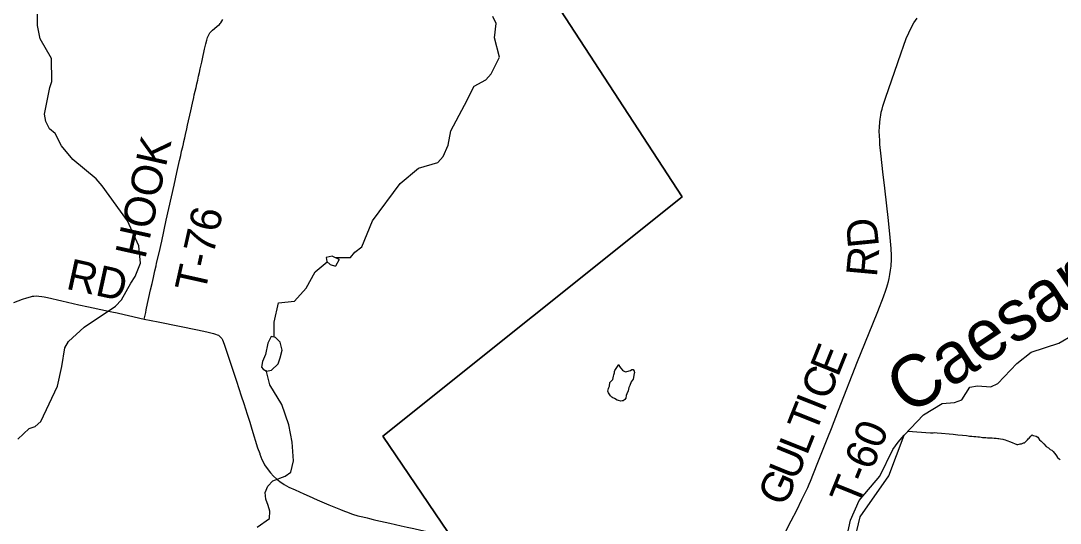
# Model space of a CAD drawing. Extents: x 1410790 to 1770854, y 448063 to 770588.
# Drawn here: x 1576526 to 1586619, y 599085 to 603957 of the extents above; entities that cross this region are included whole.
import ezdxf

# ---------------------------------------------------------------- set-up
doc = ezdxf.new("R2010")
doc.units = 0
for name, color, linetype in [('GM_X_Major_River', 7, 'Continuous'), ('GM_X_Major_River_Text', 7, 'Continuous'), ('GM_X_Minor_Lake', 7, 'Continuous'), ('GM_X_Minor_River', 7, 'Continuous'), ('GM_X_Township', 7, 'Continuous'), ('GM_X_Township_Road', 7, 'Continuous'), ('GM_X_Township_Road_Text', 7, 'Continuous')]:
    doc.layers.add(name, color=color, linetype=linetype)

msp = doc.modelspace()

# ---------------------------------------------------------------- linework, layer by layer
at = {"layer": 'GM_X_Major_River'}
for points in [[(1585103, 599938), (1585291, 600136), (1585474, 600246), (1585594, 600256), (1585665, 600280), (1585742, 600403), (1585816, 600417), (1585944, 600408), (1586013, 600441), (1586199, 600635), (1586338, 600744), (1586606, 600832), (1586872, 600985)], [(1584549, 598964), (1584584, 599114), (1584666, 599304), (1584868, 599542), (1584994, 599800), (1585047, 599871), (1585103, 599938)], [(1584615, 598887), (1584675, 599146), (1584954, 599544), (1585103, 599938)]]:
    msp.add_lwpolyline(points, dxfattribs=at)
at = {"layer": 'GM_X_Minor_Lake'}
for points in [[(1579618, 601642), (1579550, 601675), (1579492, 601660), (1579497, 601622), (1579530, 601594), (1579582, 601577)], [(1579618, 601642), (1579582, 601577)], [(1578962, 600569), (1579025, 600630), (1579046, 600690), (1579063, 600763), (1579046, 600840), (1578999, 600887), (1578957, 600896), (1578926, 600830), (1578902, 600720), (1578873, 600654)], [(1578873, 600654), (1578864, 600597), (1578878, 600578), (1578912, 600560), (1578962, 600569)], [(1582333, 600625), (1582341, 600603), (1582353, 600589), (1582369, 600569), (1582379, 600563), (1582391, 600556), (1582401, 600552), (1582411, 600556), (1582423, 600560), (1582435, 600562), (1582445, 600566), (1582459, 600574), (1582471, 600576), (1582483, 600558), (1582485, 600545), (1582483, 600535), (1582472, 600483), (1582454, 600456), (1582441, 600420), (1582431, 600400), (1582425, 600368), (1582412, 600338), (1582404, 600324), (1582400, 600296), (1582392, 600284), (1582374, 600270), (1582364, 600270), (1582354, 600268), (1582330, 600276), (1582316, 600278), (1582292, 600295), (1582276, 600301), (1582266, 600307), (1582252, 600321), (1582246, 600331), (1582234, 600350), (1582226, 600364), (1582228, 600378), (1582233, 600390), (1582235, 600400), (1582241, 600414), (1582247, 600448), (1582263, 600466), (1582274, 600477), (1582280, 600511), (1582286, 600525), (1582290, 600543), (1582292, 600555), (1582295, 600567), (1582333, 600625)]]:
    msp.add_lwpolyline(points, dxfattribs=at)
at = {"layer": 'GM_X_Minor_River'}
for points in [[(1576498, 599899), (1576606, 600002), (1576667, 600021), (1576722, 600072), (1576884, 600412), (1576923, 600604), (1576955, 600784), (1576990, 600847), (1577142, 600987), (1577445, 601190), (1577504, 601251), (1577595, 601412), (1577636, 601478), (1577690, 601607), (1577671, 601776), (1577561, 602016), (1577316, 602357), (1577259, 602426), (1577030, 602613), (1576922, 602745), (1576860, 602864), (1576804, 602909), (1576768, 602980), (1576755, 603053), (1576807, 603310), (1576826, 603370), (1576824, 603593), (1576713, 603783), (1576689, 603912), (1576689, 604022)], [(1579580, 601660), (1579728, 601660), (1579769, 601714), (1579838, 601765), (1579941, 602018), (1580211, 602378), (1580388, 602529), (1580574, 602582), (1580629, 602641), (1580677, 602751), (1580703, 602891), (1580834, 603139), (1580927, 603324), (1581041, 603386), (1581092, 603442), (1581173, 603605), (1581126, 603792), (1581142, 603930), (1581109, 603999)], [(1578985, 600890), (1578986, 601033), (1579027, 601223), (1579184, 601237), (1579296, 601363), (1579385, 601524), (1579500, 601619)], [(1578821, 599045), (1578941, 599131), (1578944, 599202), (1578927, 599256), (1578904, 599317), (1578899, 599381), (1578926, 599443), (1578973, 599494), (1579092, 599540), (1579149, 599579), (1579173, 599689), (1579160, 599872), (1579129, 600037), (1579060, 600236), (1578943, 600425), (1578910, 600570)], [(1585139, 599976), (1585360, 599960), (1585386, 599962), (1585402, 599964), (1585424, 599962), (1585466, 599957), (1585540, 599950), (1585580, 599948), (1585624, 599943), (1585670, 599939), (1585710, 599935), (1585726, 599932), (1585738, 599930), (1585748, 599930), (1585760, 599928), (1585780, 599926), (1585800, 599924), (1585820, 599921), (1585836, 599921), (1585852, 599919), (1585864, 599917), (1585879, 599917), (1585897, 599915), (1585913, 599914), (1585935, 599912), (1585957, 599912), (1585977, 599910), (1585997, 599908), (1586013, 599907), (1586023, 599907), (1586039, 599903), (1586061, 599899), (1586071, 599895), (1586083, 599893), (1586101, 599886), (1586111, 599884), (1586127, 599878), (1586137, 599874), (1586198, 599849), (1586208, 599847), (1586220, 599851), (1586231, 599853), (1586243, 599855), (1586263, 599863), (1586273, 599865), (1586285, 599878), (1586301, 599892), (1586309, 599902), (1586319, 599908), (1586334, 599930), (1586346, 599940), (1586356, 599934), (1586386, 599928), (1586402, 599919), (1586419, 599893), (1586435, 599879), (1586449, 599865), (1586461, 599855), (1586483, 599830), (1586505, 599814), (1586522, 599800), (1586536, 599792), (1586550, 599779), (1586564, 599763), (1586578, 599749), (1586582, 599739), (1586594, 599723), (1586608, 599709), (1586620, 599701)]]:
    msp.add_lwpolyline(points, dxfattribs=at)
at = {"layer": 'GM_X_Township'}
for points in [[(1587401, 595462), (1585823, 594285), (1584421, 596026), (1582893, 594860), (1582879, 594881), (1581973, 596138), (1581379, 596962), (1581560, 597014), (1581832, 596995), (1581884, 597016), (1581927, 597072), (1581946, 597129), (1580737, 598905), (1580040, 599928), (1582947, 602250), (1581717, 604136)], [(1581717, 604136), (1582947, 602250), (1580040, 599928), (1580737, 598905)]]:
    msp.add_lwpolyline(points, dxfattribs=at)
at = {"layer": 'GM_X_Township_Road'}
for points in [[(1577725, 601064), (1577739, 601129), (1577745, 601155), (1577758, 601216), (1577770, 601273), (1577787, 601347), (1577801, 601408), (1577814, 601468), (1577828, 601533), (1577839, 601581), (1577845, 601606), (1577869, 601708), (1577894, 601820), (1577939, 602025), (1577965, 602137), (1578016, 602364), (1578042, 602486), (1578068, 602601), (1578079, 602652), (1578088, 602694), (1578098, 602735), (1578105, 602764), (1578110, 602787), (1578118, 602822), (1578125, 602854), (1578139, 602911), (1578146, 602946), (1578176, 603084), (1578193, 603158), (1578206, 603215), (1578211, 603238), (1578220, 603276), (1578228, 603311), (1578237, 603346), (1578244, 603381), (1578253, 603420), (1578261, 603455), (1578269, 603493), (1578283, 603557), (1578294, 603606), (1578307, 603666), (1578311, 603682), (1578322, 603734), (1578331, 603769), (1578340, 603794), (1578345, 603807), (1578351, 603821), (1578357, 603833), (1578363, 603841), (1578375, 603855), (1578389, 603867), (1578408, 603883), (1578434, 603905), (1578455, 603923), (1578461, 603930), (1578469, 603939), (1578478, 603953), (1578487, 603971)], [(1583851, 598808), (1584006, 599108), (1584061, 599211), (1584111, 599313), (1584153, 599400), (1584168, 599432), (1584182, 599462), (1584194, 599493), (1584260, 599657), (1584273, 599691), (1584362, 599916), (1584397, 600004), (1584466, 600181), (1584651, 600653), (1584798, 601019), (1584848, 601139), (1584903, 601280), (1584926, 601345), (1584935, 601373), (1584942, 601395), (1584951, 601428), (1584958, 601458), (1584965, 601496), (1584971, 601538), (1584976, 601576), (1584981, 601645), (1584980, 601680), (1584978, 601748), (1584966, 601890), (1584949, 602050), (1584936, 602162), (1584915, 602333), (1584896, 602492), (1584881, 602643), (1584869, 602756), (1584866, 602797), (1584863, 602842), (1584862, 602886), (1584864, 602925), (1584867, 602974), (1584870, 603004), (1584876, 603043), (1584882, 603071), (1584889, 603099), (1584897, 603129), (1584927, 603216), (1585009, 603460), (1585073, 603647), (1585096, 603712), (1585123, 603786), (1585148, 603842), (1585174, 603895), (1585199, 603937), (1585231, 603983)], [(1576460, 601226), (1576543, 601256), (1576586, 601270), (1576621, 601281), (1576639, 601285), (1576653, 601287), (1576681, 601289), (1576702, 601288), (1576732, 601283), (1576752, 601280), (1576785, 601273), (1576925, 601241), (1577089, 601204), (1577185, 601183), (1577349, 601149), (1577409, 601136), (1577461, 601125), (1577531, 601109), (1577573, 601100), (1577725, 601064)], [(1577725, 601064), (1577861, 601036), (1578067, 600994), (1578241, 600959), (1578331, 600941), (1578397, 600925), (1578418, 600919), (1578434, 600913), (1578446, 600907), (1578457, 600899), (1578462, 600893), (1578469, 600885), (1578477, 600875), (1578484, 600862), (1578490, 600847), (1578504, 600812), (1578539, 600706), (1578576, 600597), (1578620, 600463), (1578667, 600321), (1578693, 600244), (1578725, 600141), (1578749, 600063), (1578769, 599998), (1578825, 599817), (1578846, 599760)], [(1578846, 599760), (1578848, 599753), (1578868, 599702), (1578879, 599681), (1578894, 599652), (1578918, 599614), (1578950, 599573), (1578980, 599542), (1579009, 599514), (1579040, 599489), (1579084, 599459), (1579129, 599434), (1579190, 599407), (1579274, 599370)], [(1579274, 599370), (1579327, 599347), (1579404, 599312), (1579518, 599264), (1579630, 599217), (1579670, 599200), (1579697, 599190), (1579720, 599181), (1579748, 599172), (1579799, 599157), (1579846, 599145), (1579888, 599135), (1579913, 599129), (1579948, 599121), (1579973, 599115), (1580111, 599084), (1580219, 599060), (1580277, 599047), (1580341, 599033), (1580412, 599018), (1580456, 599008), (1580527, 598993), (1580626, 598971), (1580698, 598956)]]:
    msp.add_lwpolyline(points, dxfattribs=at)

# ---------------------------------------------------------------- texts
at = {"layer": 'GM_X_Major_River_Text'}
msp.add_text('Caesar', height=500, rotation=33.6565, dxfattribs=at).set_placement((1585148, 600122))
at = {"layer": 'GM_X_Township_Road_Text'}
for s, rotation, p in [('HOOK', 77.3933, (1577734, 601640)), ('T-76', 77.3962, (1578313, 601308)), ('D', 95.6001, (1584860, 601771)), ('R', 84.8412, (1584838, 601466)), ('RD', 347.6323, (1576955, 601360)), ('E', 68.0147, (1584460, 600494)), ('C', 68.3631, (1584370, 600265)), ('I', 68.378, (1584324, 600151)), ('T', 68.3714, (1584242, 599942)), ('T-60', 68.0019, (1584650, 599236)), ('L', 68.3687, (1584159, 599734)), ('U', 67.848, (1584058, 599486)), ('G', 65.3625, (1583943, 599233))]:
    msp.add_text(s, height=300, rotation=rotation, dxfattribs=at).set_placement(p)

doc.saveas('drawing.dxf')
